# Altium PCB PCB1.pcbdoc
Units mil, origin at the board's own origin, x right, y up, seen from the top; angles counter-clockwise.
Board outline 4330 x 2125 mil, 2 copper layers (Top Layer, Bottom Layer), stack 62.2 mil thick; 53 components, 21 nets, 153 pads, 47 vias.
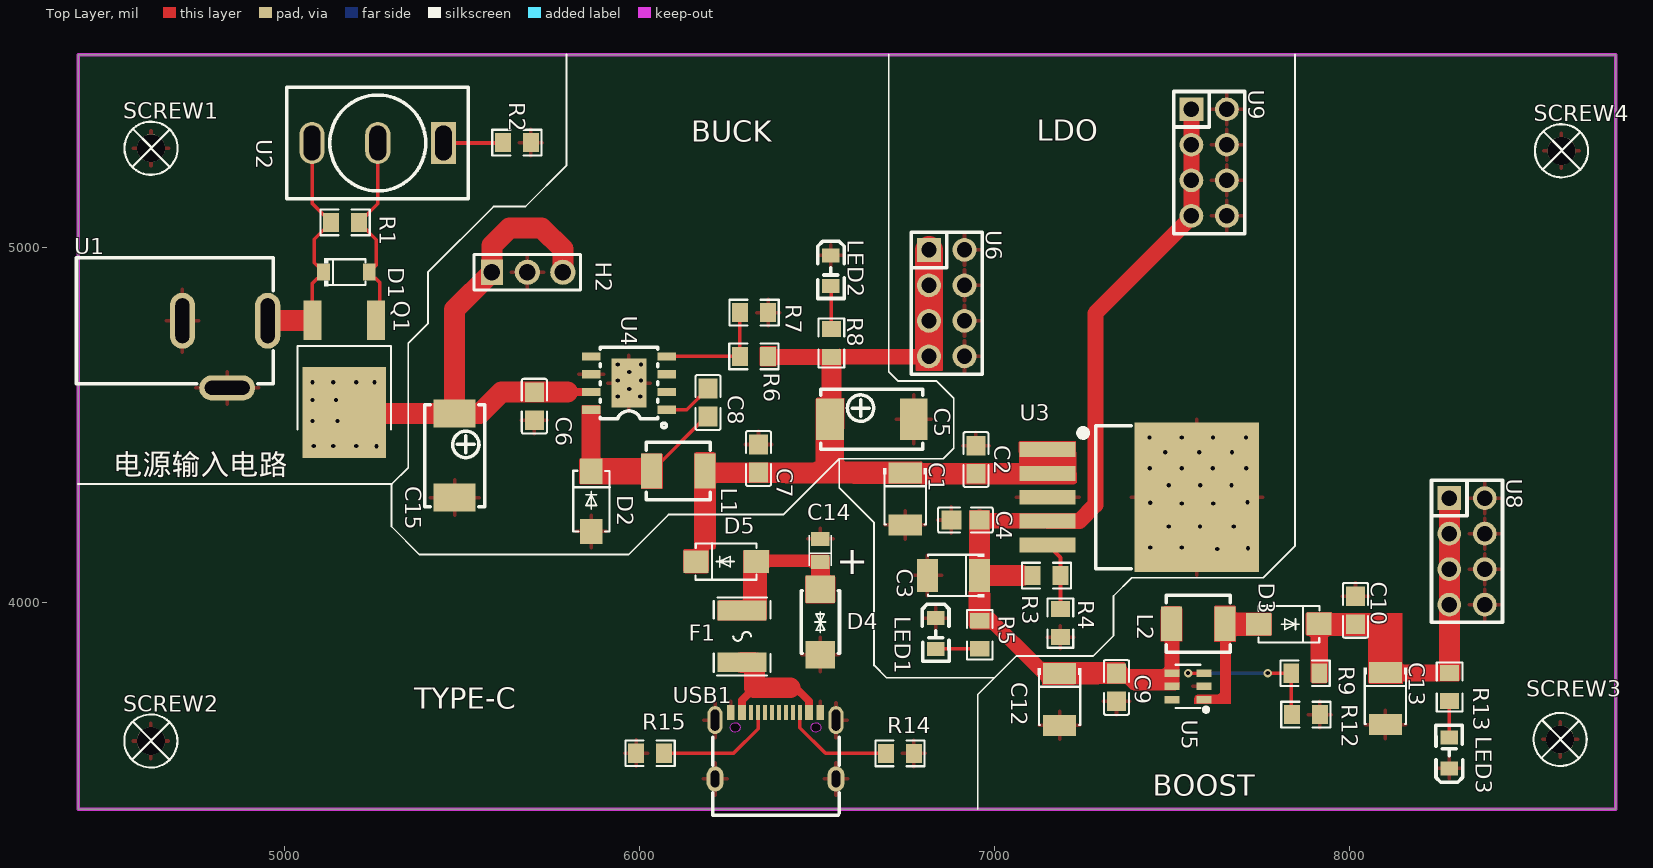
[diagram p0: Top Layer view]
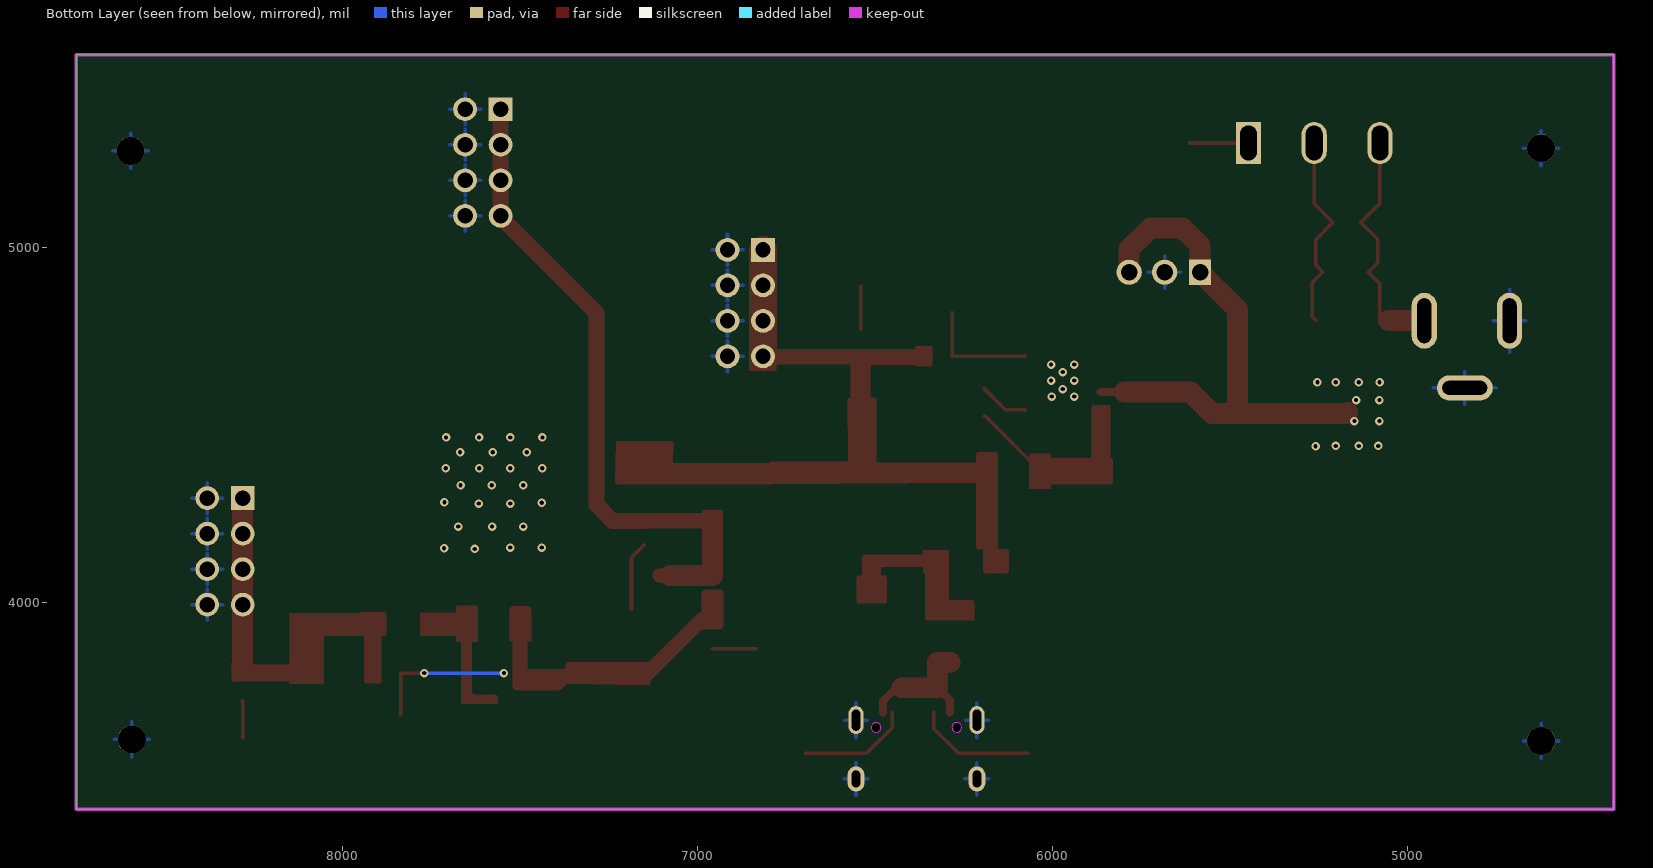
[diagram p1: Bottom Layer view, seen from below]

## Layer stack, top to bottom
Top Solder Mask Layer: solder mask 0.4, Dk 3.3
Top Layer: signal copper 1.4
Dielectric1: surface 59.4, FR4, Dk 4.5
Bottom Layer: signal copper 1.4
Bottom Solder Mask Layer: solder mask 0.4, Dk 3.3

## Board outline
4419.3,5544 4419.3,3419 8749.3,3419 8749.3,5544

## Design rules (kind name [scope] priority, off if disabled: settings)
BoardOutlineClearance copperThickness1oz [All] p0: genericclearance=10 ignorepadtopadclearanceinfootprint=FALSE except(0: Arc-SplitContinuation Track-SplitContinuation SMDPad-SplitContinuation THPad-SplitContinuation Via-SplitContinuation Fill-SplitContinuation Poly-SplitContinuation Region-SplitContinuation Text-SplitContinuation)
BoardOutlineClearance copperThickness2oz [All] p0: genericclearance=10 ignorepadtopadclearanceinfootprint=FALSE except(0: Arc-SplitContinuation Track-SplitContinuation SMDPad-SplitContinuation THPad-SplitContinuation Via-SplitContinuation Fill-SplitContinuation Poly-SplitContinuation Region-SplitContinuation Text-SplitContinuation)
BoardOutlineClearance Plane_innerPlane [All] p0: genericclearance=10 ignorepadtopadclearanceinfootprint=FALSE except(0: Arc-SplitContinuation Track-SplitContinuation SMDPad-SplitContinuation THPad-SplitContinuation Via-SplitContinuation Fill-SplitContinuation Poly-SplitContinuation Region-SplitContinuation Text-SplitContinuation)
BoardOutlineClearance Copper_copperRegion [All] p0: genericclearance=10 ignorepadtopadclearanceinfootprint=FALSE except(0: Arc-SplitContinuation Track-SplitContinuation SMDPad-SplitContinuation THPad-SplitContinuation Via-SplitContinuation Fill-SplitContinuation Poly-SplitContinuation Region-SplitContinuation Text-SplitContinuation)
BoardOutlineClearance otherClearance [All] p0: genericclearance=10 ignorepadtopadclearanceinfootprint=FALSE except(0: Arc-SplitContinuation Track-SplitContinuation SMDPad-SplitContinuation THPad-SplitContinuation Via-SplitContinuation Fill-SplitContinuation Poly-SplitContinuation Region-SplitContinuation Text-SplitContinuation)
Clearance copperThickness1oz [All] p1: gap=7 ignorepadtopadclearanceinfootprint=FALSE
Clearance copperThickness2oz [All] p1: gap=7 ignorepadtopadclearanceinfootprint=FALSE
Clearance Plane_innerPlane [All] p1: gap=7 ignorepadtopadclearanceinfootprint=FALSE
Clearance Copper_copperRegion [All] p1: gap=7 ignorepadtopadclearanceinfootprint=FALSE
Clearance otherClearance [All] p1: gap=7 ignorepadtopadclearanceinfootprint=FALSE
DiffPairsRouting differentialPair [All] p1: maxuncoupledlength=10 minlimit=6 maxlimit=Infinity mostfreqgap=6 toplayer_minwidth=5 toplayer_prefwidth=10 toplayer_maxwidth=100 bottomlayer_minwidth=5 bottomlayer_prefwidth=10 bottomlayer_maxwidth=100
PasteMaskExpansion pasteMaskExpansion [All] p1: expansion=0
PlaneConnect innerPlane [All] p1: planeconnectstyle=Relief reliefexpansion=20 reliefentries=4 reliefconductorwidth=10 reliefairgap=10
PolygonConnect copperRegion [All] p1: connectstyle=Relief reliefentries=4 reliefconductorwidth=10 polygonreliefangle="90 Angle" airgapwidth=10
RoutingVias viaSize [All] p1: viastyle="Through Hole" holewidth=12.0078 minholewidth=11.811 maxholewidth=248.0314 width=12.0078 minwidth=11.811 maxwidth=248.0314
SolderMaskExpansion solderMaskExpansion [IsVia] p1: useseparateexpansions=TRUE expansion=-1000 expansionbottom=-1000
SolderMaskExpansion solderMaskExpansion [All] p2: useseparateexpansions=TRUE expansion=2 expansionbottom=2
Width copperThickness1oz [All] p1: maxlimit=100 minlimit=5 preferedwidth=10
Width copperThickness2oz [All] p1: maxlimit=100 minlimit=8 preferedwidth=10

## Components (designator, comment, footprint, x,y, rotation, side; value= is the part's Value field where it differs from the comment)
C1 "22uF" CASE-B_3528#1 6748.3,4292.7 r270 top
C2 "100nF" C0805#1 6947.6,4403.4 r270 top
C3 "22uF" CASE-B_3528#2 6884.1,4077.4 r180 top
C4 "100nF" C0805#1 6917.9,4233.4 r0 top
C5 "100uF" CAP-SMD_L7.3-W4.3-RD_177EC0013#1 6654.3,4517 r180 top
C6 "100nF" C0805#2 5704.1,4553.8 r90 top
C7 "100nF" C0805#1 6335.2,4406.5 r270 top
C8 "10nF" C0805#3 6192.9,4564.2 r270 top
C9 "100nF" C0805#2 7343.3,3762 r90 top
C10 "100nF" C0805#3 8016.3,3979 r270 top
C12 "22uF" CASE-B_3528#1 7183.1,3728.4 r270 top
C13 "22uF" CASE-B_3528#1 8100.6,3730.4 r270 top
C14 "10uF" CAP-SMD_L2.1-W1.4-FD 6509.3,4147.7 r90 top
C15 "100uF" CAP-SMD_L7.3-W4.3-RD_177EC0013#2 5479.6,4414.8 r90 top
D1 "BZT52C16" SOD-123_L2.7-W1.6-LS3.7-RD 5174.9,4931.2 r0 top
D2 "SS54" SMA_L4.3-W2.6-LS5.0-FD#1 5864.3,4286 r90 top
D3 "SS54" SMA_L4.3-W2.6-LS5.0-FD#2 7828.7,3940.4 r0 top
D4 "SMAJ6.5CA" SMA-L4.3-W2.6-LS5.3-BI 6509.3,3946 r90 top
D5 "SS54" SMA_L4.3-W2.6-LS5.0-FD#3 6244.3,4116 r180 top
F1 "SMD1812-300-24" F1812 6289.3,3905.5 r90 top
H2 "2.54-1*3P针" HDR-TH_3P-P2.54-V-M-1 5684.3,4931 r0 top
L1 "22uH" IND-SMD_L4.6-W4.1-A 6109.3,4371 r0 top
L2 "4.7uH" IND-SMD_L4.6-W4.1-A 7573.5,3941.2 r0 top
LED1 "NCD0805R1" LED0805-RD 6834.3,3914 r270 top
LED2 "NCD0805R1" LED0805-RD 6539.3,4935 r270 top
LED3 "NCD0805R1" LED0805-RD 8280.4,3577.3 r90 top
Q1 "HY19P03D" TO-252-2_L6.6-W6.1-P4.57-LS9.9-TL-CW 5168.8,4666.1 r270 top
R1 "4.7kΩ" R0805#1 5171.2,5071.2 r180 top
R2 "1kΩ" R0805#2 5654.9,5296.2 r0 top
R3 "3.3kΩ" R0805#2 7146.3,4077 r180 top
R4 "2kΩ" R0805#2 7185.3,3943 r90 top
R5 "2kΩ" R0805#2 6958,3910.3 r90 top
R6 "6.8kΩ" R0805#3 6322.3,4694 r0 top
R7 "2.2kΩ" R0805#3 6322.8,4817.5 r180 top
R8 "2.2kΩ" R0805#2 6540.6,4731.9 r270 top
R9 "110kΩ" R0805#1 7874.7,3802 r0 top
R12 "15kΩ" R0805#1 7876.7,3685.6 r180 top
R13 "2kΩ" R0805#2 8281.3,3763 r90 top
R14 "5.1kΩ" R0805#3 6733.7,3576.1 r0 top
R15 "5.1kΩ" R0805#1 6029.9,3576.8 r180 top
SCREW1 "" M2螺丝 4624.7,5280.2 r0 top
SCREW2 "" M2螺丝 4624.3,3611 r0 top
SCREW3 "" M2螺丝 8592.7,3615.5 r0 top
SCREW4 "" M2螺丝 8596.3,5273 r0 top
U1 "DC-005-2.0" DC-IN-TH_DC-005-2.0_C22459640 4833.3,4700 r0 top
U2 "MT-0-102-A101-M200-RS" SW-TH_MT-0-103-A101-M200-RS 5263.3,5295 r180 top
U3 "SPX29302T5-L/TR" TO-263-5_L10.2-W9.9-P1.70-LS14.4-TL 7359.6,4297.4 r0 top
U4 "TPS5430DDAR" ESOP-8_L4.9-W3.9-P1.27-LS6.0-TL-EP 5970.5,4618.9 r180 top
U5 "MT3608" SOT-23-6_L2.9-W1.6-P0.95-LS2.8-BL 7544.3,3765 r90 top
U6 "HX PZ2.54-2x4P ZZ" HDR-TH_8P-P2.54-V-M-R2-C4-S2.54 6865.3,4844 r270 top
U8 "HX PZ2.54-2x4P ZZ" HDR-TH_8P-P2.54-V-M-R2-C4-S2.54 8330.3,4145 r270 top
U9 "HX PZ2.54-2x4P ZZ" HDR-TH_8P-P2.54-V-M-R2-C4-S2.54 7604.3,5240 r270 top
USB1 "TYPE-C 16PIN 2MD(073)" USB-C-SMD_TYPE-C-16PIN-2MD-073 6383.2,3597.9 r0 top

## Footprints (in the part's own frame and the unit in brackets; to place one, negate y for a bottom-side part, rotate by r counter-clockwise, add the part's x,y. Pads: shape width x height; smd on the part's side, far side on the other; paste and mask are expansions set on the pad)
C0805#1 [mil]
  rect 55.5x53.1 smd paste-3937 mask+2: 1(-39.4,0) 2(39.4,0)
  silkscreen extent -77,-36 77,36
C0805#2 [mil]
  rect 55.5x53.1 smd paste-3937 mask+2: 1(-39.3,0) 2(39.4,0)
  silkscreen extent -77,-36 77,36
C0805#3 [mil]
  rect 55.5x53.1 smd paste-3937 mask+2: 1(-39.4,0) 2(39.3,0)
  silkscreen extent -77,-36 77,36
CAP-SMD_L2.1-W1.4-FD [mil]
  rect 39.4x51.2 smd: 1(-32.5,0) 2(32.5,0)
  silkscreen extent -43,-31 43,31
CAP-SMD_L7.3-W4.3-RD_177EC0013#1 [mil]
  rect 78.7x118.1 smd paste+0 mask+2: 1(-118.1,0) 2(118.2,0)
  silkscreen extent -144,-85 144,85
CAP-SMD_L7.3-W4.3-RD_177EC0013#2 [mil]
  rect 78.7x118.1 smd paste+0 mask+2: 1(-118.2,0) 2(118.1,0)
  silkscreen extent -144,-85 144,85
CASE-B_3528#1 [mil]
  rect 59.3x93.5 smd: 1(-73.2,0) 2(73.3,0)
  silkscreen extent -87,-61 72,61
CASE-B_3528#2 [mil]
  rect 59.3x93.5 smd: 1(-73.3,0) 2(73.2,0)
  silkscreen extent -87,-61 72,61
DC-IN-TH_DC-005-2.0_C22459640 [mil]
  oval 70.9x157.5 hole 39.4 slot 126 at 90 deg: 1(120,94.5) 2(-120.1,94.5)
  oval 157.5x70.9 hole 39.4 slot 126 at 0 deg: 3(5.9,-94.5)
  silkscreen extent -419,-83 136,272
ESOP-8_L4.9-W3.9-P1.27-LS6.0-TL-EP [mil]
  rect 51.2x23.6 smd: 1(-106.3,75) 2(-106.3,25) 3(-106.3,-25) 4(-106.3,-75) 5(106.3,-75) 6(106.3,-25) 7(106.3,25) 8(106.3,75)
  rect 98.4x137.8 smd: 9(0,0)
  silkscreen extent -105,-100 81,126
F1812 [mil]
  rect 55.4x137.8 smd paste-3937 mask+2: 1(-72.9,0) 2(73,0)
  silkscreen extent -110,-80 110,80
HDR-TH_3P-P2.54-V-M-1 [mil]
  rect 62x70.9 hole 47.2: 1(-100,0)
  round 70.9 hole 47.2: 2(0,0) 3(100,0)
  silkscreen extent -150,-50 150,50
HDR-TH_8P-P2.54-V-M-R2-C4-S2.54 [mil]
  rect 66.9x66.9 hole 43.3: 1(-150,-50)
  round 66.9 hole 43.3: 2(-150,50) 3(-50,-50) 4(-50,50) 5(50,-50) 6(50,50) 7(150,-50) 8(150,50)
  silkscreen extent -200,-100 200,100
IND-SMD_L4.6-W4.1-A [mil]
  rect 59.1x98.4 smd: 1(-74.8,0) 2(74.8,0)
  silkscreen extent -91,-81 90,81
LED0805-RD [mil]
  rect 39.4x49.2 smd: 1(-43.3,0) 2(43.3,0)
  silkscreen extent -83,-37 78,38
M2螺丝 [mil]
  round 78.7 hole 78.7: 1(0,0)
  silkscreen extent -75,-75 75,75
R0805#1 [mil]
  rect 44.6x54.2 smd paste-3937 mask+2: 1(-39.4,0) 2(39.4,0)
  silkscreen extent -69,-36 69,36
R0805#2 [mil]
  rect 44.6x54.2 smd paste-3937 mask+2: 1(-39.3,0) 2(39.4,0)
  silkscreen extent -69,-36 69,36
R0805#3 [mil]
  rect 44.6x54.2 smd paste-3937 mask+2: 1(-39.4,0) 2(39.3,0)
  silkscreen extent -69,-36 69,36
SMA-L4.3-W2.6-LS5.3-BI [mil]
  rect 77.2x82.7 smd: 1(-91.7,0) 2(91.8,0)
  silkscreen extent -88,-54 88,54
SMA_L4.3-W2.6-LS5.0-FD#1 [mil]
  rect 70.9x63.8 smd: 1(-84.6,-0.3) 2(84.7,0.4)
  silkscreen extent -85,-52 86,51
SMA_L4.3-W2.6-LS5.0-FD#2 [mil]
  rect 70.9x63.8 smd: 1(-84.6,-0.4) 2(84.7,0.4)
  silkscreen extent -85,-52 86,51
SMA_L4.3-W2.6-LS5.0-FD#3 [mil]
  rect 70.9x63.8 smd: 1(-84.6,-0.4) 2(84.7,0.3)
  silkscreen extent -85,-52 86,51
SOD-123_L2.7-W1.6-LS3.7-RD [mil]
  rect 35.8x48 smd: 1(-64.3,0) 2(64.4,0)
  silkscreen extent -63,-39 54,40
SOT-23-6_L2.9-W1.6-P0.95-LS2.8-BL [mil]
  rect 20.9x42.2 smd: 1(-37.4,-45.2) 2(0,-45.2) 3(37.4,-45.2) 4(37.4,45.3) 5(0,45.3) 6(-37.4,45.3)
  silkscreen extent -72,-57 61,35
SW-TH_MT-0-103-A101-M200-RS [mil]
  rect 70.9x118.1 hole 47.2 slot 98.4 at 90 deg: 1(-185,0)
  oval 70.9x118.1 hole 47.2 slot 98.4 at 90 deg: 2(0,0) 3(185.1,0)
  silkscreen extent -255,-158 256,158
TO-252-2_L6.6-W6.1-P4.57-LS9.9-TL-CW [mil]
  rect 110.2x51.2 smd: 1(-129.6,89.5) 3(-129.6,-89.5)
  rect 255.9x236.2 smd: 2(129.6,0)
  silkscreen extent -57,-132 178,132
TO-263-5_L10.2-W9.9-P1.70-LS14.4-TL [mil]
  rect 157.5x42.1 smd: 1(-210,133.9) 2(-210,67) 3(-210,0) 4(-210,-66.9) 5(-210,-133.8)
  rect 350x419.7 smd: 6(210,0)
  silkscreen extent -120,-201 26,201
USB-C-SMD_TYPE-C-16PIN-2MD-073 [mil]
  oval 47.2x70.9 hole 23.6 slot 47.2 at 90 deg paste+0 mask+2: 13(-170.3,-93.5) 14(170.3,-93.5)
  oval 43.3x78.7 hole 23.6 slot 59.1 at 90 deg paste+0 mask+2: 13(-170.3,71.9) 14(170.3,71.9)
  rect 21.7x43.3 smd paste-3937 mask+2: A1B12(-126,93.5) A4B9(-94.5,93.5) B1A12(126,93.5) B4A9(94.5,93.5)
  rect 11.8x43.3 smd paste-3937 mask+2: A5(-49.2,93.5) A6(-9.8,93.5) A7(9.9,93.5) A8(49.2,93.5) B5(68.9,93.5) B6(29.5,93.5) B7(-29.5,93.5) B8(-68.9,93.5)
  Board Outline Layer lines w0.1: -127.4,49.8 -126.7,46.7 -125.3,43.8 -123.2,41.4 -120.6,39.5 -117.7,38.2 -114.6,37.6 -111.4,37.8 -108.3,38.7 -105.5,40.3 -103.2,42.5 -101.4,45.2 -100.3,48.2 -100,51.4 -100.3,54.6 -101.4,57.6 -103.2,60.3 -105.5,62.4 -108.3,64 -111.4,65 -114.6,65.2 -117.7,64.6 -120.6,63.3 -123.2,61.4 -125.3,59 -126.7,56.1 -127.4,53 -127.4,49.8 ; 100.1,49.8 100.9,46.7 102.3,43.8 104.3,41.4 106.9,39.5 109.9,38.2 113,37.6 116.2,37.8 119.3,38.7 122,40.3 124.4,42.5 126.1,45.2 127.2,48.2 127.6,51.4 127.2,54.6 126.1,57.6 124.4,60.3 122,62.4 119.3,64 116.2,65 113,65.2 109.9,64.6 106.9,63.3 104.3,61.4 102.3,59 100.9,56.1 100.1,53 100.1,49.8
  Board Outline Layer region: -100,51.4 -100.3,48.2 -101.4,45.2 -103.2,42.5 -105.5,40.3 -108.3,38.7 -111.4,37.8 -114.6,37.6 -117.7,38.2 -120.6,39.5 -123.2,41.4 -125.3,43.8 -126.7,46.7 -127.4,49.8 -127.4,53 -126.7,56.1 -125.3,59 -123.2,61.4 -120.6,63.3 -117.7,64.6 -114.6,65.2 -111.4,65 -108.3,64 -105.5,62.4 -103.2,60.3 -101.4,57.6 -100.3,54.6
  Board Outline Layer region: -100,51.4 -100.3,48.2 -101.4,45.2 -103.2,42.5 -105.5,40.3 -108.3,38.7 -111.4,37.8 -114.6,37.6 -117.7,38.2 -120.6,39.5 -123.2,41.4 -125.3,43.8 -126.7,46.7 -127.4,49.8 -127.4,53 -126.7,56.1 -125.3,59 -123.2,61.4 -120.6,63.3 -117.7,64.6 -114.6,65.2 -111.4,65 -108.3,64 -105.5,62.4 -103.2,60.3 -101.4,57.6 -100.3,54.6
  Board Outline Layer region: 127.6,51.4 127.2,48.2 126.1,45.2 124.4,42.5 122,40.3 119.3,38.7 116.2,37.8 113,37.6 109.9,38.2 106.9,39.5 104.3,41.4 102.3,43.8 100.9,46.7 100.1,49.8 100.1,53 100.9,56.1 102.3,59 104.3,61.4 106.9,63.3 109.9,64.6 113,65.2 116.2,65 119.3,64 122,62.4 124.4,60.3 126.1,57.6 127.2,54.6
  Board Outline Layer region: 127.6,51.4 127.2,48.2 126.1,45.2 124.4,42.5 122,40.3 119.3,38.7 116.2,37.8 113,37.6 109.9,38.2 106.9,39.5 104.3,41.4 102.3,43.8 100.9,46.7 100.1,49.8 100.1,53 100.9,56.1 102.3,59 104.3,61.4 106.9,63.3 109.9,64.6 113,65.2 116.2,65 119.3,64 122,62.4 124.4,60.3 126.1,57.6 127.2,54.6
  Multi-Layer board cut-out: -100,51.4 -100.3,48.2 -101.4,45.2 -103.2,42.5 -105.5,40.3 -108.3,38.7 -111.4,37.8 -114.6,37.6 -117.7,38.2 -120.6,39.5 -123.2,41.4 -125.3,43.8 -126.7,46.7 -127.4,49.8 -127.4,53 -126.7,56.1 -125.3,59 -123.2,61.4 -120.6,63.3 -117.7,64.6 -114.6,65.2 -111.4,65 -108.3,64 -105.5,62.4 -103.2,60.3 -101.4,57.6 -100.3,54.6
  Multi-Layer board cut-out: 127.6,51.4 127.2,48.2 126.1,45.2 124.4,42.5 122,40.3 119.3,38.7 116.2,37.8 113,37.6 109.9,38.2 106.9,39.5 104.3,41.4 102.3,43.8 100.9,46.7 100.1,49.8 100.1,53 100.9,56.1 102.3,59 104.3,61.4 106.9,63.3 109.9,64.6 113,65.2 116.2,65 119.3,64 122,62.4 124.4,60.3 126.1,57.6 127.2,54.6
  silkscreen extent -177,-196 180,24

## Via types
v1: diameter 24, hole 12, Top Layer to Bottom Layer, 47 vias

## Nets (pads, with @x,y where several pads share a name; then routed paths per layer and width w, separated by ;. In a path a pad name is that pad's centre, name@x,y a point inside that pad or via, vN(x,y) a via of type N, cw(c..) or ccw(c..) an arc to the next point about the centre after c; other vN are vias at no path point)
3.3V: C3.1 C4.2 C9.2 C12.1 L2.1 R3.2 R5.2 U3.4 U5.4 U5.5 U9.1 U9.3 U9.5 U9.7 | length 1685
  Top Layer w39.4: 7076.6,4077.4 7106.5,4077.4 R3.2
  Top Layer w45.3: U3.4 7238.6,4230.5 7283.9,4275.8 7283.9,4815.4 7554.3,5085.8 U9.7 U9.5 U9.3 U9.1
  Top Layer w59.1: C4.2 6957.3,4077.6 C3.1 7076.6,4077.4
$1N10: R2.1 U2.1 | length 167.8
  Top Layer w10: U2.1 5614.3,5295 R2.1
$1N11: D1.2 Q1.1 R1.1 U2.2 | length 565.8
  Top Layer w10: Q1.1 5268.3,4805.7 5268.3,4902.3 D1.2 5259.3,4951.2 5259.3,5022.6 R1.1 5263.3,5123.9 U2.2
$1N14: D1.1 Q1.3 R1.2 U1.1 U2.3 | length 666
  Top Layer w10: U2.3 5078.2,5124.9 R1.2 5084.3,5023.7 5084.3,4957.6 D1.1 5079.3,4900 Q1.3
  Top Layer w59.1: U1.1 Q1.3@5054.3,4794.5
$1N17: LED1.2 R5.1 | length 123.9
  Top Layer w10: LED1.2 6957.8,3870.7 R5.1
$1N18: R3.1 R4.2 U3.5 | length 196.2
  Top Layer w10: U3.5 7185.6,4127.6 R3.1 7185.6,3982.8 R4.2
$1N32: C8.2 D2.2 L1.1 U4.8 | length 222.2
  Top Layer w10: L1.1 6188.3,4524.9 C8.2
$1N34: C8.1 U4.1 | length 140.8
  Top Layer w10: U4.1 6133.2,4543.9 C8.1
$1N35: R6.1 R7.2 U4.4 | length 329.9
  Top Layer w10: U4.4 6282.7,4693.9 R6.1 6282.9,4816.9 R7.2
$1N40: LED2.2 R8.1 | length 121
  Top Layer w10: LED2.2 6540.6,4890.4 R8.1
$1N43: D3.1 L2.2 U5.1
$1N45: R9.1 R12.2 U5.3 | length 452.6
  Top Layer w10: v1(7544.8,3802.4) U5.3 ; v1(7769.3,3802.4) 7834.9,3802.4 R9.1 7835.3,3687.6 R12.2
  Bottom Layer w10: v1(7544.8,3802.4) v1(7769.3,3802.4)
$1N48: LED3.2 R13.1 | length 103.5
  Top Layer w10: LED3.2 8280.4,3722.8 R13.1
$1N53: R15.1 USB1.A5 | length 339.2
  Top Layer w10: R15.1 6265,3576.8 6334.3,3646 6334.3,3691.2 USB1.A5
$1N55: R14.1 USB1.B5 | length 315.6
  Top Layer w10: USB1.B5 6451.8,3691.1 6451.8,3648.4 6524.1,3576.1 R14.1
$1N57: C14.1 D4.2 D5.1 F1.2
+5V: C10.2 C13.1 D3.2 R9.2 R13.2 U8.1 U8.3 U8.5 U8.7 | length 493
  Top Layer w47.2: R13.2 8281.3,3827.6
  Top Layer w59.1: U8.1 8281.3,4294 8281.3,3827.6
GND: C1.2 C2.1 C3.2 C4.1 C5.1 C6.1 C7.1 C9.1 C10.1 C12.2 C13.2 C14.2 C15.1 D2.1 D4.1 H2.2 LED1.1 LED2.1 LED3.1 R2.2 R4.1 R7.1 R12.1 R14.2 R15.2 SCREW1.1 SCREW2.1 SCREW3.1 SCREW4.1 U1.2 U1.3 U3.3 U3.6 U4.6 U4.9 U5.2 U6.2 U6.4 U6.6 U6.8 U8.2 U8.4 U8.6 U8.8 U9.2 U9.4 U9.6 U9.8 USB1.13 USB1.14 USB1.A1B12 USB1.B1A12
  other v1: 7627.3,4152 7713.3,4154 7438.3,4155.8 7527.3,4155.8 7490.6,4215 7578.2,4215 7673.3,4215 7527.3,4279.6 7615.5,4279.6 7438.3,4282 7712.3,4283 7490.6,4331.5 7579.5,4331.5 7667.1,4331.5 7437.3,4379 7527.3,4379 7614.5,4379 7708.7,4379 7480.3,4424 7576.1,4424 7668.3,4424 7436.3,4466 7527.3,4466 7614.9,4466 7707.7,4466 5939.3,4581 6002.3,4581 5971.3,4602 5939.3,4626 6004.3,4626 5971.3,4650 5939.3,4671 6004.3,4671
TYPE-C-5V: F1.1 USB1.A4B9 USB1.B4A9 | length 383.6
  Top Layer w21.7: USB1.A4B9 6288.7,3725.5 6324.3,3761 ; 6434.3,3766 6477.7,3722.6 USB1.B4A9
  Top Layer w59.1: F1.1 6324.3,3832.6 6324.3,3761 6424.3,3761
VBAT+: C6.2 C15.2 H2.1 H2.3 Q1.2 U4.7 | length 1549.3
  Top Layer w23.6: 5797.4,4593.9 U4.7
  Top Layer w59.1: Q1.2 5172.4,4532.9 C15.2 ; H2.3 5784.3,4996 5724.3,5056 5634.3,5056 5584.3,5006 H2.1 5479.6,4826.4 C15.2 ; 5797.4,4593.9 5796.8,4593.2 C6.2 5611.4,4593.2 5551.1,4532.9 C15.2
  other v1: 5259.3,4441 5083.2,4441.8 5137.6,4441.8 5202.6,4441.8 5079.7,4512 5149.9,4512 5079.7,4571 5145.5,4571 5079.3,4621 5137.6,4621 5202.6,4621 5254.3,4621
VCC5V: C1.1 C2.2 C5.2 C7.2 D5.2 L1.2 R6.2 R8.2 U3.1 U3.2 U6.1 U6.3 U6.5 U6.7 | length 300
  Top Layer w78.7: U6.7 U6.5 U6.3 U6.1
pads on no net: U4.2 U4.3 U4.5 U5.6 USB1.A6 USB1.A7 USB1.A8 USB1.B6 USB1.B7 USB1.B8

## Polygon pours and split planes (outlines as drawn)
GND on Top Layer (solid, remove dead copper, pour order 0): 3000,5866.1 3000,3000 9520,3000 9520,5866.1
GND on Bottom Layer (solid, remove dead copper, pour order 2): 3815.3,5794 3815.3,3074.7 9017.9,3074.7 9017.9,5794

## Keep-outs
Board Outline Layer:
  the board outline again, w10

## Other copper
Top Layer:
  region net $1N32: 5890.3,4553 5890.3,4410 5890.5,4408.9 5891.1,4407.9 5892.1,4407.3 5893.3,4407 6001.9,4407.6 6003,4407.8 6004,4408.4 6004.6,4409.4 6004.8,4410.5 6004.9,4417.1 6005.1,4418.2 6005.8,4419.2 6006.8,4419.8 6007.9,4420 6062.3,4420 6063.4,4419.8 6064.4,4419.1 6065,4418.2 6065.3,4417 6065.3,4323.8 6065,4322.6 6064.4,4321.7 6063.4,4321 6062.3,4320.8 6007.8,4320.8 6006.7,4321 6005.7,4321.7 6005.1,4322.7 6004.8,4323.8 6004.9,4331.1 6004.7,4332.2 6004,4333.2 6003.1,4333.9 6001.9,4334.1 5834.2,4334.1 5833,4334.3 5832.1,4335 5831.4,4336 5831.2,4337.1 5831.2,4403.6 5831.4,4404.7 5832.1,4405.7 5833,4406.3 5834.2,4406.6 5835.4,4406.8 5836.4,4407.4 5837,4408.4 5837.3,4409.6 5837.3,4553 5837.5,4554.2 5838.1,4555.1 5839.1,4555.8 5840.3,4556 5887.3,4556 5888.4,4555.8 5889.4,4555.1 5890,4554.2
  region net $1N57: 6220.3,3950.6 6220.2,3950.6 6220.2,4001.7 6220.6,4003.6 6221.7,4005.2 6223.3,4006.3 6225.2,4006.7 6287.4,4006.7 6289.3,4007.1 6290.9,4008.2 6292,4009.8 6292.4,4011.7 6292.4,4143.7 6292.8,4145.6 6293.8,4147.3 6295.5,4148.3 6297.4,4148.7 6365.2,4148.8 6365.2,4148.7 6365.2,4135.4 6365.3,4135.5 6530.2,4135.5 6532.1,4135.1 6533.7,4134.1 6534.8,4132.4 6535.2,4130.5 6535.3,4081.7 6535.6,4079.8 6536.7,4078.2 6538.4,4077.1 6540.3,4076.7 6546,4076.7 6547.9,4076.3 6549.5,4075.3 6550.6,4073.6 6551,4071.7 6550.9,4003.8 6550.6,4001.9 6549.5,4000.3 6547.9,3999.2 6545.9,3998.8 6472.3,3998.8 6470.4,3999.2 6468.8,4000.3 6467.7,4001.9 6467.3,4003.8 6467.4,4071.7 6467.7,4073.6 6468.8,4075.2 6470.4,4076.3 6472.4,4076.7 6483.2,4076.7 6483.1,4076.8 6483.1,4095.6 6482.8,4097.5 6481.7,4099.1 6480.1,4100.2 6478.2,4100.6 6369.6,4101.5 6367.7,4101.2 6366.1,4100.1 6365,4098.5 6364.6,4096.5 6364.6,4084.1 6358.6,4084.2 6358.6,3955.6 6358.2,3953.7 6357.1,3952.1 6355.5,3951 6353.6,3950.6
  region net 3.3V: 7228.6,4246.9 7228.6,4209.4 7228.1,4209 6989.1,4209.9 6987,4207.9 6987,4206.9 6986.5,4206.3 6929.2,4206.3 6928.7,4206.9 6928.7,4259.6 6930.2,4261.1 6984.4,4261.1 6986.5,4259.1 6986.5,4251.9 7223.6,4251.9 7225.5,4251.5 7227.1,4250.4 7228.2,4248.8
  region net VCC5V: 6149.3,4151 6151.2,4151.4 6152.8,4152.5 6153.9,4154.1 6154.3,4156 6154.3,4418.5 6154.6,4420.4 6155.7,4422.1 6157.3,4423.1 6159.3,4423.5 6209.3,4423.5 6211.2,4423.1 6212.8,4422.1 6213.9,4420.4 6214.3,4418.5 6214.3,4395.1 6491.3,4396.5 6493.2,4396.9 6494.8,4398 6495.9,4399.6 6496.3,4401.5 6496.3,4572 6496.6,4573.9 6497.7,4575.6 6499.3,4576.7 6501.2,4577 6508.1,4577.1 6510,4577.4 6511.6,4578.5 6512.7,4580.1 6513.1,4582 6513.3,4665 6512.9,4666.9 6511.8,4668.6 6510.2,4669.6 6508.3,4670 6385.4,4670.2 6385.4,4666.7 6343.8,4666.3 6341.9,4666.7 6340.2,4667.8 6339.1,4669.4 6338.7,4671.3 6338.7,4717 6339.1,4718.9 6340.1,4720.6 6341.8,4721.7 6343.7,4722 6384.9,4722.2 6384.9,4714.7 6563.3,4714.9 6563.9,4714.9 6564.5,4714.8 6854.4,4715 6854.4,4655 6852.3,4653.7 6779.2,4653.7 6777.7,4654.9 6777.6,4670.8 6776.1,4672.1 6568.3,4670.8 6568,4670.2 6568.3,4576.5 6576.8,4576.5 6575.7,4402.9 6576.1,4400.9 6577.2,4399.3 6578.8,4398.2 6580.8,4397.8 6791.7,4398.5 6793.6,4398.1 6795.3,4397 6796.3,4395.4 6796.7,4393.5 6796.7,4392.6 7064.8,4392.6 7068.9,4394.2 7068.4,4452.6 7070.4,4454.7 7228.1,4454.6 7229.1,4453.5 7231.1,4338.4 7224.9,4334.3 6793.4,4334.3 6793,4334.2 6792.6,4334.1 6792.1,4334.1 6791.7,4334.1 6219.3,4338 6217.3,4337.6 6215.7,4336.5 6214.6,4334.9 6214.3,4333 6214.3,4156 6213.9,4154.1 6212.8,4152.5 6211.2,4151.4 6209.3,4151 6195.4,4151 6195.3,4150.8 6195.3,4091 6195,4088.6 6194,4086.5 6192.3,4084.7 6190.3,4083.5 6128.8,4083.5 6126.7,4084.7 6125,4086.5 6124,4088.6 6123.8,4091 6123.8,4146 6124.1,4147.9 6125.2,4149.6 6126.8,4150.6 6128.8,4151
  region net 3.3V: 7224,3769.7 7223.2,3769.6 7222.3,3769.5 7133.8,3769.5 7133.8,3775.4 7133.4,3778 7132.4,3780.4 7130.8,3782.5 6990.2,3923.1 6988.1,3924.7 6985.7,3925.7 6983.1,3926 6937.8,3926 6935.2,3926.4 6932.8,3927.4 6930.7,3929 6929.1,3931 6928.1,3933.4 6927.8,3936 6927.8,4032.5 6932.8,4037.5 6977.3,4037.5 6979.8,4037.2 6982.3,4036.2 6984.3,4034.6 6985.9,4032.5 6986.9,4030.1 6987.3,4027.5 6987.3,3972.5 6992.6,3972.5 6995.2,3972.2 6997.6,3971.2 6999.7,3969.6 7132.8,3836.5 7134.9,3834.9 7137.3,3833.9 7139.9,3833.5 7222.3,3833.5 7222.5,3833.5 7222.7,3833.5 7223,3833.5 7223.2,3833.5 7360.4,3833.5 7362.9,3833.2 7365.4,3832.2 7367.4,3830.6 7369,3828.5 7370,3826.1 7370.4,3823.5 7370.7,3820.9 7371.7,3818.5 7373.3,3816.4 7375.4,3814.8 7377.8,3813.8 7380.4,3813.5 7469.1,3813.5 7471.7,3813.8 7474.1,3814.8 7476.2,3816.4 7477.8,3818.5 7478.8,3820.9 7479.1,3823.5 7479.4,3891.6 7468.6,3891.6 7468.6,3980.9 7469,3983.5 7470,3985.9 7471.6,3987.9 7473.6,3989.5 7476,3990.5 7478.6,3990.9 7518.5,3990.9 7521.1,3990.5 7523.5,3989.5 7525.6,3987.9 7527.2,3985.9 7528.2,3983.5 7528.5,3980.9 7528.5,3891.6 7520.3,3891.6 7520.3,3764.4 7520,3761.8 7519,3759.4 7517.4,3757.3 7515.3,3755.7 7512.9,3754.8 7510.3,3754.4 7390.9,3754.4 7388.3,3754.8 7385.9,3755.7 7383.8,3757.3 7371.3,3769.8 7369.8,3771.1 7368,3772 7366,3772.6 7364,3772.7 7224,3769.7
  region net $1N43: 7635.4,3751 7635.4,3890.5 7618.3,3890.5 7618.3,3987 7618.6,3988.9 7619.7,3990.6 7621.3,3991.6 7623.3,3992 7673.8,3992 7675.7,3991.6 7677.3,3990.6 7678.4,3988.9 7678.8,3987 7678.8,3977.5 7679.1,3975.6 7680.2,3974 7681.8,3972.9 7683.8,3972.5 7775.3,3972.5 7777.2,3972.1 7778.8,3971.1 7779.9,3969.4 7780.3,3967.5 7780.3,3912.6 7779.9,3910.7 7778.8,3909.1 7777.2,3908 7775.3,3907.6 7683.8,3907.6 7681.8,3907.3 7680.2,3906.2 7679.1,3904.6 7678.8,3902.6 7678.8,3890.5 7664.8,3890.5 7664.8,3716 7664.3,3715.5 7563.3,3715.5 7562.8,3716 7562.8,3731 7563.1,3733.6 7564.1,3736 7565.7,3738.1 7567.8,3739.7 7570.2,3740.7 7572.8,3741 7625.4,3741 7628,3741.4 7630.4,3742.4 7632.5,3744 7634.1,3746 7635.1,3748.4
  region net +5V: 8310.6,3830.3 8310.6,3785.5 8310.3,3783.7 8309.4,3782 8308.1,3780.7 8306.4,3779.8 8304.6,3779.5 8148.8,3779.5 8148.8,3772.5 8057.8,3772.5 8056,3772.8 8054.3,3773.7 8053,3775 8052.1,3776.7 8051.8,3778.5 8051.8,3901 8051.5,3902.9 8050.7,3904.6 8049.4,3905.9 8047.7,3906.7 8045.8,3907 7943.8,3907 7941.9,3906.7 7940.2,3905.9 7938.9,3904.6 7938,3902.9 7937.8,3901 7937.8,3780 7937.5,3778.2 7936.6,3776.5 7935.3,3775.2 7933.6,3774.3 7931.8,3774 7896.8,3774 7894.9,3774.3 7893.2,3775.2 7891.9,3776.5 7891,3778.2 7890.8,3780 7890.8,3901 7890.5,3902.9 7889.6,3904.6 7888.3,3905.9 7886.6,3906.7 7884.8,3907 7882.3,3907 7880.4,3907.3 7878.7,3908.2 7877.4,3909.5 7876.5,3911.2 7876.3,3913 7876.3,3967.6 7876.5,3969.4 7877.4,3971.1 7878.7,3972.4 7880.4,3973.3 7882.3,3973.6 7949.8,3973.6 7949.8,3970.5 8148.3,3970.5 8147.8,3970 8147.8,3832 8148,3830.2 8148.9,3828.5 8150.2,3827.2 8151.9,3826.3 8153.8,3826 8253,3826 8253,3836.3 8304.6,3836.3 8306.4,3836 8308.1,3835.2 8309.4,3833.8 8310.3,3832.2

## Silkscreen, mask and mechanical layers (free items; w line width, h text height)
Top Silkscreen Layer:
  lines w5: 4419.3,4334.8 5303.1,4334.8 5349.3,4381 5349.3,4731 5404.3,4786 5404.3,4931 5589.3,5116 5679.3,5116 5794.3,5231 5794.3,5544 ; 5301.8,4334.8 5301.8,4215 5380.8,4136 5969.3,4136 6081.8,4248.5 6405.3,4248.5 6562.8,4406 ; 6701.8,5545 6701.8,4651 6728.3,4624.5 6836.8,4624.5 6884.8,4576.5 6884.8,4435.5 6855.3,4406 6562.8,4406 ; 6952.6,3419 6952.6,3741.9 6999.8,3789 ; 7846.3,5544 7846.3,4159.5 7845.3,4159.5 7756.8,4071 7386.3,4071 7334.8,4019.5 7334.8,3907.5 7277.8,3850.5 7061.3,3850.5 6999.8,3789 ; 6562.8,4406 6562.8,4324 6660.8,4226 6660.8,3824 6695.8,3789 6999.8,3789
  text "LDO" at 7118.8,5301.5 h60
  text "BUCK" at 6145.3,5298.5 h60
  text "电源输入电路" at 4519.3,4361 h60
  text "+" at 6554.3,4081 h78.7
  text "TYPE-C" at 5365.8,3701.5 h60
  text "BOOST" at 7445.8,3457 h60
